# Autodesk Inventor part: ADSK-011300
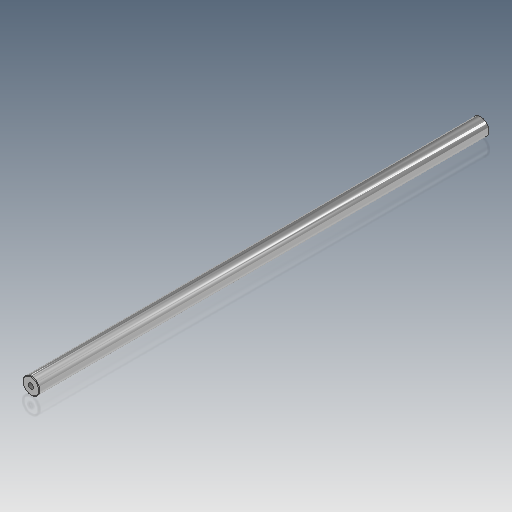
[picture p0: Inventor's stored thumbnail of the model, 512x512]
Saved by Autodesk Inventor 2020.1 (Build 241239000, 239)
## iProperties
Created: 1999-11
Part Number: ADSK-011300
Description: SHFTTA,RC,AX,340,12,EE,SHAFT,VERTICAL
Document SubType Name: Modeling
Designer: sspink
Material: Générique
Density: 1 g/cm^3
Appearance: Chrom - poliert
Mass: 690.232 g
Surface Area: 905.251 cm^2
Volume: 690.232 cm^3
Control State: 0
Checked Out: False
Last Check In By: sspink
Last Check In Date: 1999-12-22
Master: False
Shininess: 0.0
Length Units: 11269
Angle Units: 11279
Time Units: 11290
Mass Units: 11283
Length Display Precision: 3
Angle Display Precision: 2
Compacted: True
Dimensions: 32x32x865 mm
Mass: 0,69 kg
DocNumber: ADSK-011300.ipt
Folder: 01 - Themengebiete\Simplification\01 - Packaging machine\
VDS_Category: 3D Komponenten
Density: 0.0
Volumn: 0.0
Area: 0.0
PropertySet Name: Model Information
Author: sspink
Revision Number: -
Title: SHFTTA,RC,AX,340,12,EE,SHAFT,VERTICAL
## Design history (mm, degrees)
node "Solide1"
  node "Extrusion1" dims "d1" = 865, "d2" = 0
  node "Hole1" dims "d3" = 10.106, "d4" = 9.525, "d5" = 6.35, "d6" = 60 deg, "d7" = 32.3, "d8" = 118 deg, "d18" = 24
  node "Hole2" dims "d9" = 10.106, "d10" = 9.525, "d11" = 6.35, "d12" = 60 deg, "d13" = 32.3, "d14" = 118 deg, "d19" = 24
  node "Chamfer1" dims "d15" = 1, "d16" = 1, "d17" = 45 deg
sketch "Sketch1"
  geometry: C1 r 16 at (0, 0)
  constraints: 1 centre point, 1 other
  dimensions: "d0" = 32 diameter of C1
node "Corps solides"
node "Corps surfaciques"
sketch "Sketch2"
  geometry: C1 r 16 at (0, 0) reference; 1 further point
  constraints: 1 coincident
sketch "Sketch4"
  geometry: C1 r 16 at (0, 0) reference; 1 further point
  constraints: 1 coincident
